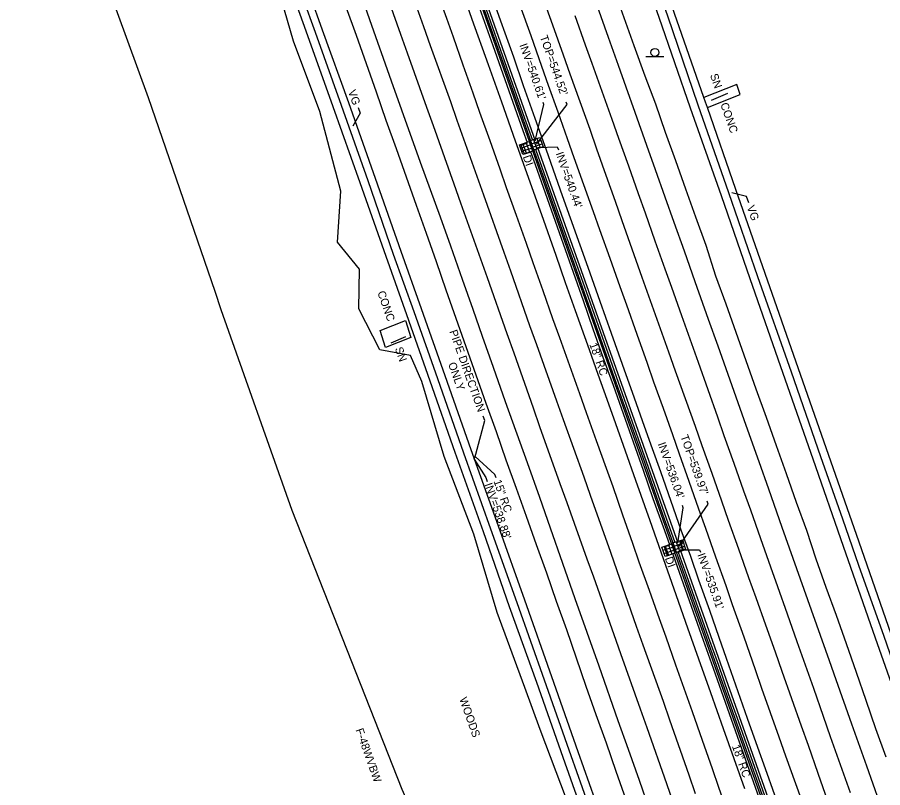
# Model space of a CAD drawing. Extents: x 2004847 to 2009016, y 1134161 to 1140101.
# Drawn here: x 2006408.5 to 2006840.8, y 1134706.5 to 1135091.3 of the extents above; entities that cross this region are included whole.
import ezdxf

# ---------------------------------------------------------------- set-up
doc = ezdxf.new("R2010")
doc.units = 0
for name, color, linetype in [('RD_EX_BldgApp', 7, 'Continuous'), ('RD_EX_Conc', 7, 'Continuous'), ('RD_EX_DR_Inlet', 7, 'Continuous'), ('RD_EX_DR_Inlet_txCode', 7, 'Continuous'), ('RD_EX_DR_Pipe', 7, 'Continuous'), ('RD_EX_DR_Pipe_txCode', 7, 'Continuous'), ('RD_EX_Fence_Other', 7, 'Continuous'), ('RD_EX_Pavement_Markings', 7, 'Continuous'), ('RD_EX_Road', 7, 'Continuous'), ('RD_EX_VEG', 7, 'Continuous'), ('RD_Sketch3', 7, 'Continuous')]:
    doc.layers.add(name, color=color, linetype=linetype)

msp = doc.modelspace()

# ---------------------------------------------------------------- linework, layer by layer
at = {"layer": 'RD_EX_BldgApp'}
for p, q in [((2006722.49, 1135071.69), (2006731.49, 1135071.69)), ((2006763.35, 1135053.23), (2006755.15, 1135049.76)), ((2006595.2, 1134928.68), (2006602.69, 1134931.83))]:
    msp.add_line(p, q, dxfattribs=at)
msp.add_circle((2006727.01, 1135073.71), 2, dxfattribs=at)
at = {"layer": 'RD_EX_Conc'}
for points in [[(2006675.5, 1134761.9), (2006661.98, 1134800.2), (2006648.88, 1134837.03), (2006635.24, 1134875.26), (2006622.18, 1134912.27), (2006610.37, 1134945.6), (2006600.33, 1134974.35), (2006587.41, 1135010.83), (2006574.1, 1135048.61), (2006561.06, 1135084.93), (2006548.68, 1135119.62), (2006535.39, 1135157.35), (2006523.68, 1135190.43), (2006511.28, 1135225.98), (2006498.12, 1135263.32), (2006485.4, 1135299.36), (2006470.96, 1135339.94), (2006458.29, 1135375.71), (2006443.5, 1135416.97)], [(2006668.03, 1134759.07), (2006654.39, 1134796.86), (2006641.41, 1134834.32), (2006627.28, 1134873.89), (2006614.7, 1134909.55), (2006603.05, 1134942.58), (2006592.79, 1134971.85), (2006579.8, 1135008.61), (2006566.37, 1135046.54), (2006553.72, 1135081.99), (2006541.38, 1135116.41), (2006527.8, 1135154.96), (2006516.15, 1135187.81), (2006503.49, 1135224.19), (2006490.61, 1135260.58), (2006477.77, 1135296.55), (2006463.47, 1135336.86), (2006450.32, 1135374.25), (2006436.35, 1135413.3)], [(2007008.76, 1134333.65), (2006993.63, 1134363.82), (2006975.89, 1134409.97), (2006965.78, 1134441.02), (2006950.02, 1134485.15), (2006934.64, 1134528.55), (2006918.96, 1134572.55), (2006904.01, 1134614.93), (2006889.45, 1134656.34), (2006873.52, 1134701.79), (2006859.53, 1134740.78), (2006845, 1134783.14), (2006828.98, 1134829.04), (2006813.77, 1134872.83), (2006798.81, 1134915.62), (2006782.15, 1134963.38), (2006767.46, 1135005.24), (2006753.34, 1135046.25), (2006752.31, 1135048.89), (2006751.51, 1135051.2), (2006736.87, 1135093.18), (2006721.7, 1135136.82), (2006709.9, 1135170.59)], [(2007001.61, 1134330.02), (2006986.35, 1134360.57), (2006969.5, 1134406.75), (2006958.22, 1134438.26), (2006942.49, 1134482.23), (2006927.03, 1134526.16), (2006911.49, 1134569.75), (2006896.31, 1134613.04), (2006882.16, 1134653.08), (2006865.99, 1134699.12), (2006852.4, 1134738.21), (2006837.28, 1134781.15), (2006821.3, 1134826.88), (2006806.03, 1134870.56), (2006791.16, 1134913.28), (2006774.61, 1134960.65), (2006760.24, 1135002.17), (2006744.89, 1135045.85), (2006729.14, 1135091.12), (2006713.78, 1135134.81), (2006702.17, 1135168.35)], [(2006641.02, 1135097.08), (2006646.02, 1135082.91), (2006651.02, 1135068.84), (2006656.04, 1135054.66), (2006661.03, 1135040.52), (2006666.66, 1135024.46), (2006671.67, 1135010.36), (2006676.69, 1134996.22), (2006681.72, 1134982.09), (2006686.7, 1134967.95), (2006691.71, 1134953.82), (2006696.74, 1134939.67), (2006701.68, 1134925.57), (2006706.73, 1134911.38), (2006711.73, 1134897.29), (2006716.78, 1134883.09), (2006721.78, 1134869), (2006726.73, 1134854.87), (2006731.72, 1134840.72), (2006737.75, 1134823.75), (2006742.75, 1134809.65), (2006747.75, 1134795.47), (2006752.75, 1134781.39), (2006757.72, 1134767.21), (2006762.74, 1134753.08), (2006767.73, 1134738.9), (2006772.71, 1134724.78), (2006777.73, 1134710.65), (2006782.72, 1134696.51)], [(2006640.36, 1135096.84), (2006645.37, 1135082.67), (2006650.38, 1135068.61), (2006655.4, 1135054.43), (2006660.37, 1135040.29), (2006666, 1135024.23), (2006671.01, 1135010.12), (2006676.02, 1134995.98), (2006681.06, 1134981.86), (2006686.04, 1134967.71), (2006691.05, 1134953.58), (2006696.07, 1134939.42), (2006701.02, 1134925.34), (2006706.05, 1134911.14), (2006711.06, 1134897.05), (2006716.07, 1134882.83), (2006721.06, 1134868.74), (2006726.05, 1134854.63), (2006731.03, 1134840.48), (2006737.06, 1134823.51), (2006742.04, 1134809.4), (2006747.01, 1134795.21), (2006752.01, 1134781.13), (2006757, 1134766.95), (2006762.04, 1134752.83), (2006767, 1134738.64), (2006771.99, 1134724.52), (2006777.01, 1134710.4), (2006782, 1134696.25)], [(2006753.34, 1135046.25), (2006769.62, 1135052.78), (2006767.89, 1135057.68), (2006751.51, 1135051.2)], [(2006592.51, 1134926.31), (2006589.87, 1134934.81), (2006602.52, 1134939.82)], [(2006602.52, 1134939.82), (2006605.17, 1134931.32), (2006592.51, 1134926.31)], [(2006812.01, 1134352.55), (2006804.85, 1134390.29), (2006793.78, 1134426.87), (2006781.64, 1134461.67), (2006769.18, 1134497.73), (2006756.9, 1134532.82), (2006743.7, 1134570.21), (2006731.7, 1134604.22), (2006718.31, 1134641.74), (2006713.33, 1134655.71), (2006700.01, 1134692.45), (2006688.72, 1134724.37), (2006675.5, 1134761.9)], [(2006804.07, 1134351.71), (2006797.18, 1134388.56), (2006786.48, 1134424.09), (2006774.14, 1134459.12), (2006761.55, 1134495.03), (2006749.36, 1134530.2), (2006736.12, 1134567.64), (2006724.06, 1134601.67), (2006710.86, 1134638.74), (2006705.69, 1134653.17), (2006692.76, 1134689), (2006681.14, 1134721.57), (2006668.03, 1134759.07)]]:
    msp.add_lwpolyline(points, dxfattribs=at)
at = {"layer": 'RD_EX_DR_Inlet'}
for p, q in [((2006661.08, 1135028.1), (2006662.7, 1135023.37)), ((2006662.68, 1135028.65), (2006664.31, 1135023.92)), ((2006665.39, 1135028.06), (2006670.12, 1135029.68)), ((2006665.94, 1135026.45), (2006670.67, 1135028.07)), ((2006666.45, 1135030.22), (2006668.07, 1135025.49)), ((2006668.06, 1135030.77), (2006669.68, 1135026.04)), ((2006660.02, 1135025.94), (2006664.75, 1135027.56)), ((2006660.57, 1135024.33), (2006665.3, 1135025.95)), ((2006737.63, 1134829.25), (2006739.25, 1134824.53)), ((2006739.24, 1134829.81), (2006740.86, 1134825.08)), ((2006731.12, 1134825.05), (2006735.85, 1134826.67)), ((2006731.67, 1134823.44), (2006736.4, 1134825.06)), ((2006732.17, 1134827.21), (2006733.8, 1134822.48)), ((2006733.78, 1134827.76), (2006735.4, 1134823.03)), ((2006736.58, 1134827.1), (2006741.31, 1134828.72)), ((2006737.13, 1134825.49), (2006741.86, 1134827.11))]:
    msp.add_line(p, q, dxfattribs=at)
for points in [[(2006661.09, 1135022.82), (2006659.47, 1135027.55), (2006664.2, 1135029.17), (2006665.82, 1135024.44)], [(2006666.46, 1135024.93), (2006664.84, 1135029.66), (2006669.57, 1135031.29), (2006671.19, 1135026.56)], [(2006737.65, 1134823.97), (2006736.02, 1134828.7), (2006740.75, 1134830.33), (2006742.38, 1134825.6)], [(2006732.19, 1134821.93), (2006730.57, 1134826.66), (2006735.3, 1134828.28), (2006736.92, 1134823.55)]]:
    msp.add_lwpolyline(points, close=True, dxfattribs=at)
at = {"layer": 'RD_EX_DR_Inlet_txCode'}
for points in [[(2006667.2, 1135029.63), (2006671.61, 1135047.76), (2006671.29, 1135048.69)], [(2006667.8, 1135027.98), (2006683.17, 1135047.68), (2006682.76, 1135048.83)], [(2006668.4, 1135026.31), (2006678.28, 1135026.61), (2006678.84, 1135025.02)], [(2006637.65, 1134873.1), (2006642.08, 1134889.8), (2006641.31, 1134891.97)], [(2006636.82, 1134870.55), (2006642.62, 1134861.39), (2006643.3, 1134859.45)], [(2006738.4, 1134828.71), (2006741.18, 1134846.22), (2006740.74, 1134847.48)], [(2006738.98, 1134826.99), (2006753.58, 1134848.13), (2006753.05, 1134849.64)], [(2006739.57, 1134825.25), (2006749.29, 1134825.33), (2006749.73, 1134824.08)]]:
    msp.add_lwpolyline(points, dxfattribs=at)
at = {"layer": 'RD_EX_DR_Pipe'}
for p, q in [((2006602.9, 1135212), (2006667.2, 1135029.63)), ((2006668.4, 1135026.31), (2006738.4, 1134828.71)), ((2006636.82, 1134870.55), (2006637.65, 1134873.1)), ((2006739.57, 1134825.25), (2006809.6, 1134627.85))]:
    msp.add_line(p, q, dxfattribs=at)
at = {"layer": 'RD_EX_DR_Pipe_txCode'}
msp.add_lwpolyline([(2006647.71, 1134861.27), (2006647.14, 1134862.89), (2006637.26, 1134871.91)], dxfattribs=at)
at = {"layer": 'RD_EX_Fence_Other'}
for points in [[(2006510.38, 1134945.08), (2006507.34, 1134954.31), (2006474.12, 1135050.98), (2006442.39, 1135137.92), (2006413.57, 1135223.26), (2006408.53, 1135238.79)], [(2006781.02, 1134257.51), (2006758.13, 1134323.34), (2006734.53, 1134389.26), (2006705.85, 1134470.16), (2006673.2, 1134545.85), (2006633.71, 1134630.78), (2006600.8, 1134705.61), (2006545.88, 1134844.85), (2006510.38, 1134945.08)]]:
    msp.add_lwpolyline(points, dxfattribs=at)
at = {"layer": 'RD_EX_Pavement_Markings'}
for points in [[(2006601.47, 1135114.83), (2006611.47, 1135086.72), (2006614.84, 1135077.13), (2006624.87, 1135049.27), (2006628.1, 1135039.88), (2006638.08, 1135011.95), (2006641.33, 1135002.55), (2006651.63, 1134973.89), (2006654.82, 1134964.6), (2006664.46, 1134937.36), (2006667.82, 1134927.83), (2006677.94, 1134899.63), (2006681.2, 1134890.34), (2006691.48, 1134861.81), (2006694.75, 1134852.52), (2006704.78, 1134824.06), (2006707.94, 1134814.9), (2006717.65, 1134787.22), (2006721.02, 1134777.75), (2006731.11, 1134749.72), (2006734.29, 1134740.34), (2006743.96, 1134712.87), (2006747.16, 1134703.49)], [(2006639.69, 1135118.11), (2006649.82, 1135089.5), (2006656.31, 1135071.46), (2006661.25, 1135057.22), (2006667.07, 1135040.83), (2006673.56, 1135022.74), (2006675.07, 1135018.4), (2006680.76, 1135002.34), (2006693.51, 1134966.47), (2006699.53, 1134949.47), (2006705.25, 1134933.52), (2006710.63, 1134918), (2006716.68, 1134901.14), (2006721.66, 1134886.97), (2006725.7, 1134875.93), (2006729.8, 1134864.42), (2006740.06, 1134835.31), (2006744.73, 1134822.12), (2006748.87, 1134810.27), (2006754.22, 1134795.19), (2006758.9, 1134781.66), (2006762.63, 1134771.13), (2006773.12, 1134741.27), (2006777.5, 1134729.02), (2006782.95, 1134713.64), (2006788.58, 1134697.68)], [(2006589.93, 1135111.21), (2006600.01, 1135082.88), (2006603.31, 1135073.46), (2006612.88, 1135046.47), (2006616.18, 1135037.18), (2006626.6, 1135008.12), (2006629.87, 1134998.55), (2006639.91, 1134970.67), (2006643.31, 1134961.34), (2006653.12, 1134933.3), (2006656.56, 1134923.6), (2006666.23, 1134896.17), (2006669.46, 1134886.88), (2006679.6, 1134858.33), (2006683, 1134848.9), (2006693.08, 1134820.84), (2006696.3, 1134811.85), (2006706.52, 1134783.06), (2006709.91, 1134773.49), (2006719.7, 1134745.81), (2006723.01, 1134736.47), (2006732.74, 1134708.5), (2006736.01, 1134699.34)], [(2006839.16, 1134699.2), (2006832.85, 1134717.15), (2006825.38, 1134738.24), (2006817.49, 1134760.27), (2006814.19, 1134769.86), (2006803.44, 1134800.3), (2006790.68, 1134836.48), (2006784.02, 1134855.5), (2006779.12, 1134869.19), (2006772.62, 1134887.43), (2006767.62, 1134901.5), (2006758.58, 1134927), (2006753.84, 1134940.26), (2006747.15, 1134959.07), (2006741.76, 1134974.38), (2006736.62, 1134988.82), (2006732.11, 1135001.38), (2006727.27, 1135015.01), (2006723.03, 1135027.16), (2006717.11, 1135043.72), (2006712.7, 1135056.3), (2006708.87, 1135067.14), (2006703.89, 1135081.11), (2006693.9, 1135109.51)], [(2006579.6, 1135104.1), (2006584.41, 1135090.24), (2006595.24, 1135059.54), (2006600.39, 1135045.1), (2006609.84, 1135018.85), (2006619.7, 1134991.69), (2006624.88, 1134977.18), (2006630.83, 1134960.42), (2006636.08, 1134945.48), (2006640.82, 1134932.05), (2006646.2, 1134916.6), (2006652.29, 1134899.37), (2006663.19, 1134868.88), (2006669.31, 1134851.65), (2006674.76, 1134836.23), (2006687.1, 1134800.99), (2006699.01, 1134767.27), (2006708.56, 1134739.98), (2006713.64, 1134725.77), (2006719.13, 1134710.22), (2006724, 1134696.26)], [(2006617.96, 1135104.74), (2006622.86, 1135090.8), (2006626.19, 1135081.45), (2006631.13, 1135067.5), (2006636.07, 1135053.55), (2006639.49, 1135043.83), (2006644.49, 1135029.73), (2006649.49, 1135015.62), (2006652.81, 1135006.29), (2006657.72, 1134992.41), (2006662.64, 1134978.53), (2006666.08, 1134968.8), (2006671.01, 1134954.77), (2006675.94, 1134940.75), (2006679.33, 1134931.33), (2006684.36, 1134917.33), (2006689.38, 1134903.32), (2006692.66, 1134893.91), (2006697.67, 1134879.96), (2006702.68, 1134866), (2006705.95, 1134856.84), (2006710.86, 1134842.76), (2006715.78, 1134828.68), (2006719.06, 1134819.31), (2006724.1, 1134805.15), (2006729.14, 1134790.99), (2006732.43, 1134781.79), (2006737.36, 1134767.84), (2006742.29, 1134753.88), (2006745.65, 1134744.54), (2006750.62, 1134730.28), (2006755.58, 1134716.02), (2006758.78, 1134706.76), (2006763.78, 1134692.6)], [(2006630.34, 1135105.37), (2006635.62, 1135090.29), (2006643.66, 1135067.74), (2006650.32, 1135049.13), (2006657.22, 1135029.65), (2006670.37, 1134992.76), (2006677.5, 1134972.5), (2006682.28, 1134958.73), (2006687.25, 1134944.83), (2006694.15, 1134925.35), (2006698.56, 1134912.96), (2006703, 1134900.57), (2006707.27, 1134888.32), (2006712.11, 1134874.79), (2006717.29, 1134860.02), (2006724.42, 1134839.93), (2006731.12, 1134820.98), (2006736.53, 1134805.73), (2006743.33, 1134786.38), (2006748.74, 1134770.9), (2006754.76, 1134754.04), (2006761.15, 1134736.06), (2006771.82, 1134705.98)], [(2006670.57, 1135102.53), (2006675.85, 1135087.54), (2006681.14, 1135072.54), (2006684.58, 1135062.97), (2006689.51, 1135049.2), (2006694.44, 1135035.42), (2006697.87, 1135025.53), (2006702.5, 1135012.45), (2006707.13, 1134999.38), (2006710.48, 1134989.86), (2006715.52, 1134975.67), (2006720.56, 1134961.48), (2006723.84, 1134952.17), (2006728.83, 1134938.2), (2006733.82, 1134924.22), (2006737.23, 1134914.66), (2006742.16, 1134900.86), (2006747.09, 1134887.07), (2006750.52, 1134877.32), (2006755.39, 1134863.55), (2006760.27, 1134849.79), (2006763.63, 1134840.17), (2006768.72, 1134825.8), (2006773.81, 1134811.43), (2006777.4, 1134801.43), (2006782.22, 1134787.87), (2006787.04, 1134774.3), (2006790.4, 1134764.68), (2006795.24, 1134751.03), (2006800.08, 1134737.37), (2006803.56, 1134727.63), (2006808.44, 1134713.79), (2006813.32, 1134699.95)], [(2006659.58, 1135097.4), (2006665, 1135082.11), (2006670.43, 1135066.82), (2006673.74, 1135057.41), (2006678.48, 1135044.04), (2006683.23, 1135030.67), (2006686.56, 1135021.3), (2006691.34, 1135007.8), (2006696.12, 1134994.3), (2006699.37, 1134985.24), (2006704.43, 1134971.04), (2006709.49, 1134956.84), (2006712.79, 1134947.59), (2006717.94, 1134933.06), (2006723.09, 1134918.52), (2006726.4, 1134909.23), (2006731.11, 1134896.03), (2006735.82, 1134882.82), (2006739.17, 1134873.31), (2006744.02, 1134859.54), (2006748.88, 1134845.76), (2006752.23, 1134836.1), (2006757.31, 1134821.74), (2006762.4, 1134807.39), (2006765.7, 1134797.95), (2006771.39, 1134781.76), (2006777.07, 1134765.56), (2006780.32, 1134756.21), (2006784.64, 1134744.04), (2006788.97, 1134731.86), (2006792.32, 1134722.46), (2006797.26, 1134708.59), (2006802.21, 1134694.72)], [(2006687.11, 1135092.11), (2006692.26, 1135077.55), (2006695.5, 1135068.29), (2006700.5, 1135054.37), (2006705.5, 1135040.45), (2006708.9, 1135030.92), (2006713.78, 1135017.11), (2006718.65, 1135003.3), (2006722.12, 1134993.64), (2006727.07, 1134979.66), (2006732.02, 1134965.68), (2006735.33, 1134956.42), (2006740.31, 1134942.37), (2006745.29, 1134928.32), (2006748.62, 1134918.94), (2006753.43, 1134905.36), (2006758.24, 1134891.79), (2006761.54, 1134882.36), (2006766.44, 1134868.54), (2006771.35, 1134854.72), (2006774.71, 1134845.2), (2006779.74, 1134830.96), (2006784.76, 1134816.71), (2006788.23, 1134806.99), (2006793.09, 1134793.26), (2006797.95, 1134779.54), (2006801.24, 1134770.23), (2006806.18, 1134756.19), (2006811.12, 1134742.14), (2006814.62, 1134732.08), (2006819.59, 1134718.06), (2006824.56, 1134704.05)]]:
    msp.add_lwpolyline(points, dxfattribs=at)
at = {"layer": 'RD_EX_Road'}
msp.add_line((2006738.68, 1134824.19), (2006741.34, 1134825.06), dxfattribs=at)
for points in [[(2006601.85, 1135210.84), (2006601.93, 1135210.61), (2006606.96, 1135196.5), (2006611.94, 1135182.34), (2006616.92, 1135168.16), (2006621.91, 1135154.04), (2006627.01, 1135139.98), (2006632.02, 1135125.79), (2006637.05, 1135111.69), (2006641.95, 1135097.51), (2006646.91, 1135083.33), (2006651.95, 1135069.26), (2006656.96, 1135055.1), (2006661.96, 1135040.96), (2006665.85, 1135029.87)], [(2006663.4, 1135028.58), (2006661.28, 1135034.53), (2006656.24, 1135048.66), (2006651.29, 1135062.83), (2006646.27, 1135076.96), (2006641.24, 1135091.08), (2006636.22, 1135105.18), (2006631.25, 1135119.39), (2006626.24, 1135133.47), (2006621.21, 1135147.65), (2006616.24, 1135161.8), (2006611.24, 1135175.94), (2006606.26, 1135190.01), (2006601.23, 1135204.15), (2006599.46, 1135209.23)], [(2006706.11, 1135169.52), (2006717.88, 1135136.12), (2006733.28, 1135092.09), (2006748.47, 1135047.58), (2006763.79, 1135003.81), (2006778.27, 1134961.83), (2006795.07, 1134914.22), (2006809.69, 1134871.89), (2006820.71, 1134840.68), (2006828.76, 1134817.54), (2006841.37, 1134782.12), (2006855.99, 1134739.87), (2006869.8, 1134700.59), (2006885.78, 1134654.79), (2006900.16, 1134613.89), (2006915.32, 1134570.8), (2006930.8, 1134527.38), (2006946.57, 1134483.83), (2006961.99, 1134439.72), (2006972.66, 1134408.4), (2006989.95, 1134362.61), (2007005.15, 1134331.63)], [(2006544.96, 1135117.94), (2006557.24, 1135083.84), (2006570.3, 1135047.45), (2006583.57, 1135009.68), (2006596.31, 1134972.97), (2006606.65, 1134944.38), (2006618.49, 1134910.8), (2006631.4, 1134873.68), (2006644.94, 1134835.73), (2006658.11, 1134798.96), (2006671.71, 1134760.39), (2006684.95, 1134722.62), (2006696.29, 1134690.56)], [(2006706.48, 1135105.36), (2006711.58, 1135091.25), (2006716.49, 1135077.13), (2006721.97, 1135062.08), (2006727.26, 1135048), (2006732.23, 1135033.93), (2006737.32, 1135019.73), (2006742.27, 1135005.65), (2006747.35, 1134991.55), (2006752.46, 1134977.4), (2006757.35, 1134962.2), (2006762.48, 1134948.11), (2006767.52, 1134934), (2006772.43, 1134919.8), (2006777.49, 1134905.68), (2006782.53, 1134891.57), (2006787.62, 1134877.47), (2006792.57, 1134863.33), (2006797.67, 1134849.15), (2006802.74, 1134835.06), (2006807.45, 1134820.82), (2006812.38, 1134806.66), (2006817.57, 1134792.59), (2006822.65, 1134778.48), (2006827.55, 1134764.22), (2006832.33, 1134750.14), (2006837.27, 1134735.95), (2006842.31, 1134721.82)], [(2006572.67, 1135096.57), (2006577.75, 1135082.41), (2006582.79, 1135068.28), (2006587.83, 1135054.13), (2006592.58, 1135039.87), (2006597.76, 1135025.79), (2006602.79, 1135011.64), (2006607.8, 1134997.51), (2006612.78, 1134983.41), (2006617.81, 1134969.3), (2006622.62, 1134955.13), (2006627.64, 1134940.98), (2006632.61, 1134926.88), (2006637.64, 1134912.7), (2006642.61, 1134898.55), (2006647.66, 1134884.39), (2006652.61, 1134870.24), (2006657.65, 1134856.14), (2006662.74, 1134842.04), (2006667.71, 1134827.92), (2006672.92, 1134813.86), (2006677.69, 1134799.64), (2006682.82, 1134785.52), (2006687.69, 1134771.34), (2006692.48, 1134757.15), (2006697.52, 1134743.03), (2006702.64, 1134728.87), (2006707.58, 1134714.75), (2006712.54, 1134700.63)], [(2006665.06, 1135023.97), (2006661.93, 1135022.88), (2006660.28, 1135027.48), (2006663.4, 1135028.58)], [(2006734.46, 1134827.77), (2006731.31, 1134836.6), (2006726.2, 1134850.71), (2006721.32, 1134864.87), (2006716.3, 1134879.04), (2006711.33, 1134893.14), (2006706.29, 1134907.31), (2006701.25, 1134921.42), (2006696.26, 1134935.56), (2006691.3, 1134949.73), (2006686.32, 1134963.82), (2006681.29, 1134977.97), (2006676.29, 1134992.11), (2006671.32, 1135006.28), (2006666.32, 1135020.42), (2006665.06, 1135023.97)], [(2006667.41, 1135025.38), (2006667.59, 1135024.9), (2006672.58, 1135010.78), (2006677.59, 1134996.64), (2006682.6, 1134982.51), (2006687.64, 1134968.38), (2006692.67, 1134954.26), (2006697.68, 1134940.11), (2006702.67, 1134926.02), (2006707.66, 1134911.82), (2006712.69, 1134897.73), (2006717.67, 1134883.51), (2006722.7, 1134869.43), (2006727.66, 1134855.3), (2006732.65, 1134841.15), (2006737, 1134828.9)], [(2006741.34, 1134825.06), (2006739.77, 1134829.82), (2006737, 1134828.9)], [(2006736.07, 1134823.23), (2006733.38, 1134822.3), (2006731.76, 1134826.84), (2006734.46, 1134827.77)], [(2006805.41, 1134627.07), (2006802.4, 1134635.38), (2006797.44, 1134649.54), (2006796.3, 1134652.82), (2006791.21, 1134666.89), (2006786.29, 1134681.06), (2006781.31, 1134695.21), (2006776.32, 1134709.37), (2006771.34, 1134723.51), (2006766.31, 1134737.64), (2006761.28, 1134751.77), (2006756.29, 1134765.92), (2006751.32, 1134780.04), (2006746.33, 1134794.18), (2006741.34, 1134808.35), (2006736.33, 1134822.48), (2006736.07, 1134823.23)], [(2006738.68, 1134824.19), (2006743.68, 1134810.08), (2006748.69, 1134795.91), (2006753.69, 1134781.82), (2006758.72, 1134767.66), (2006763.7, 1134753.52), (2006768.72, 1134739.36), (2006773.7, 1134725.23), (2006778.72, 1134711.1), (2006783.71, 1134696.96), (2006788.76, 1134682.81), (2006793.68, 1134668.67), (2006798.72, 1134654.54), (2006804.15, 1134639.5), (2006808.12, 1134628.08)]]:
    msp.add_lwpolyline(points, dxfattribs=at)
at = {"layer": 'RD_EX_VEG'}
msp.add_lwpolyline([(2006682.82, 1134700.75), (2006669.68, 1134735.59), (2006662.03, 1134756.48), (2006648.16, 1134794.05), (2006636.63, 1134833.04), (2006621.76, 1134871.87), (2006610.63, 1134909.35), (2006604.89, 1134922.32), (2006589.62, 1134925.19), (2006579.21, 1134945.59), (2006579.43, 1134965.42), (2006568.47, 1134978.99), (2006570.11, 1135004.49), (2006559.7, 1135044.26), (2006546.5, 1135079.4), (2006536.33, 1135114.43)], dxfattribs=at)
at = {"layer": 'RD_Sketch3'}
for points in [[(2006578.76, 1135046.21), (2006579.77, 1135043.37), (2006576.15, 1135036.82)], [(2006773.99, 1134998.53), (2006772.85, 1135001.77), (2006765.53, 1135003.67)]]:
    msp.add_lwpolyline(points, dxfattribs=at)

# ---------------------------------------------------------------- texts
at = {"layer": 'RD_EX_DR_Inlet_txCode'}
for s, p in [("TOP=544.52'", (2006669.48, 1135081.53)), ("INV=540.61'", (2006659.29, 1135077.42)), ("INV=540.44'", (2006677.41, 1135023.26)), ('DI', (2006661, 1135021.62)), ('PIPE DIRECTION', (2006624.31, 1134934.37)), ('ONLY', (2006623.67, 1134918.18)), ("TOP=539.97'", (2006739.7, 1134881.98)), ("INV=536.04'", (2006728.41, 1134878.22)), ("INV=538.88'", (2006641.86, 1134857.93)), ('DI', (2006731.94, 1134821.05)), ("INV=535.91'", (2006748.16, 1134822.83))]:
    msp.add_text(s, height=4, rotation=289.4494, dxfattribs=at).set_placement(p)
at = {"layer": 'RD_EX_DR_Pipe_txCode'}
for s, p in [('18" RC', (2006694.24, 1134927.9)), ('15" RC', (2006646.36, 1134859.58)), ('18" RC', (2006765.46, 1134727.2))]:
    msp.add_text(s, height=4, rotation=289.4494, dxfattribs=at).set_placement(p)
at = {"layer": 'RD_Sketch3'}
for s, p in [('SN', (2006754.49, 1135062.35)), ('VG', (2006573.67, 1135054.27)), ('CONC', (2006759.63, 1135047.87)), ('VG', (2006772.88, 1134996.54)), ('CONC', (2006588.3, 1134953.83)), ('SN', (2006597.07, 1134925.84)), ('WOODS', (2006629.23, 1134750.83)), ('F-48WVBW', (2006577.43, 1134735.34))]:
    msp.add_text(s, height=4, rotation=289.4494, dxfattribs=at).set_placement(p)

doc.saveas('drawing.dxf')
